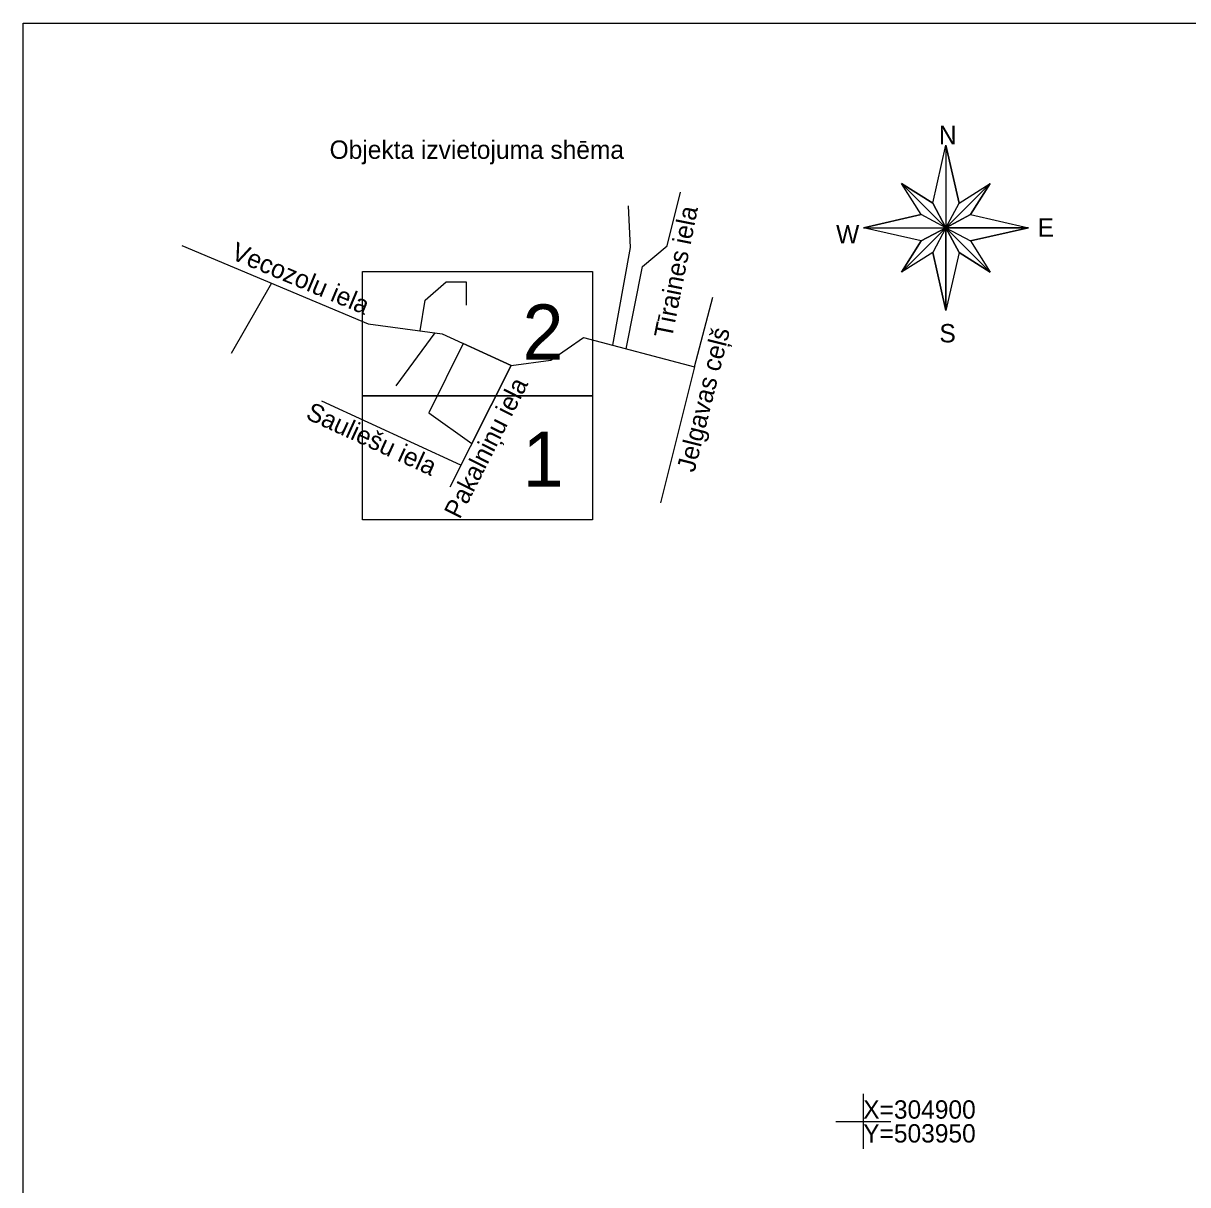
# Model space of a CAD drawing. Extents: x 503904 to 504094, y 304688 to 304960.
# Drawn here: x 503904.2 to 503967.7, y 304896.6 to 304959.8 of the extents above; entities that cross this region are included whole.
import ezdxf

# ---------------------------------------------------------------- set-up
doc = ezdxf.new("R2010")
doc.units = 0
for name, color, linetype in [('GEOD_ELEM_####_####_#', 7, 'Continuous'), ('GEOD_KORD_####_TKST_#', 7, 'Continuous'), ('RAMI_PLAN_####_TKST_#', 7, 'Continuous')]:
    doc.layers.add(name, color=color, linetype=linetype)

msp = doc.modelspace()

# ---------------------------------------------------------------- linework, layer by layer
at = {"layer": 'GEOD_ELEM_####_####_#'}
for p, q in [((503950, 304901.5), (503950, 304900)), ((503948.5, 304900), (503950, 304900)), ((503950, 304900), (503950, 304898.5)), ((503950, 304900), (503951.5, 304900))]:
    msp.add_line(p, q, dxfattribs=at)
at = {"layer": 'RAMI_PLAN_####_TKST_#'}
for p, q in [((503954.508, 304953.205), (503954.508, 304944.205)), ((503952.095, 304951.118), (503956.921, 304946.293)), ((503953.789, 304950.053), (503954.508, 304948.705)), ((503954.508, 304948.705), (503955.227, 304950.053)), ((503954.508, 304948.705), (503953.16, 304949.424)), ((503955.856, 304949.424), (503954.508, 304948.705)), ((503950.008, 304948.705), (503959.008, 304948.705)), ((503953.16, 304947.987), (503954.508, 304948.705)), ((503954.508, 304948.705), (503953.789, 304947.357)), ((503954.508, 304948.705), (503955.856, 304947.987)), ((503955.227, 304947.357), (503954.508, 304948.705)), ((503917.735, 304945.692), (503915.539, 304941.845)), ((503926.641, 304942.987), (503924.513, 304940.087)), ((503930.814, 304941.2), (503927.462, 304934.576)), ((503940.803, 304941.129), (503938.952, 304933.723)), ((503928.067, 304935.772), (503920.48, 304939.249))]:
    msp.add_line(p, q, dxfattribs=at)
for points in [[(503904.204, 304959.85), (504093.703, 304959.85), (504093.703, 304823.741), (503904.204, 304823.741)], [(503956.921, 304946.293), (503955.227, 304947.357), (503954.508, 304944.205), (503953.789, 304947.357), (503952.095, 304946.293), (503953.16, 304947.987), (503950.008, 304948.705), (503953.16, 304949.424), (503952.095, 304951.118), (503953.789, 304950.053), (503954.508, 304953.205), (503955.227, 304950.053), (503956.921, 304951.118), (503955.856, 304949.424), (503959.008, 304948.705), (503955.856, 304947.987)], [(503922.704, 304946.315), (503935.239, 304946.315), (503935.239, 304939.549), (503922.704, 304939.549)], [(503928.19, 304942.406), (503926.319, 304938.613), (503928.662, 304936.947), (503930.814, 304941.2)], [(503922.704, 304939.549), (503935.239, 304939.549), (503935.239, 304932.782), (503922.704, 304932.782)]]:
    msp.add_lwpolyline(points, close=True, dxfattribs=at)
for points in [[(503954.508, 304948.705), (503955.227, 304950.053), (503954.508, 304953.205), (503954.508, 304948.705)], [(503956.921, 304951.118), (503952.095, 304946.293)], [(503954.508, 304948.705), (503953.789, 304950.053), (503952.095, 304951.118), (503954.508, 304948.705)], [(503954.508, 304948.705), (503955.856, 304949.424), (503956.921, 304951.118), (503954.508, 304948.705)], [(503937.071, 304942.11), (503937.963, 304946.587), (503939.319, 304947.727), (503940.037, 304950.643)], [(503936.35, 304942.299), (503937.312, 304947.632), (503937.204, 304949.91)], [(503954.508, 304948.705), (503953.16, 304949.424), (503950.008, 304948.705), (503954.508, 304948.705)], [(503954.508, 304948.705), (503953.16, 304947.987), (503952.095, 304946.293), (503954.508, 304948.705)], [(503954.508, 304948.705), (503953.789, 304947.357), (503954.508, 304944.205), (503954.508, 304948.705)], [(503954.508, 304948.705), (503955.856, 304947.987), (503959.008, 304948.705), (503954.508, 304948.705)], [(503954.508, 304948.705), (503955.227, 304947.357), (503956.921, 304946.293), (503954.508, 304948.705)], [(503912.847, 304947.743), (503923.008, 304943.479), (503927.042, 304942.933), (503930.814, 304941.2), (503932.973, 304941.485), (503934.753, 304942.719), (503940.803, 304941.129), (503941.802, 304944.931)], [(503925.843, 304943.095), (503926.113, 304944.767), (503927.265, 304945.757), (503928.35, 304945.757), (503928.35, 304944.496)]]:
    msp.add_lwpolyline(points, dxfattribs=at)

# ---------------------------------------------------------------- texts
at = {"layer": 'GEOD_KORD_####_TKST_#'}
for s, p in [('X=304900', (503950, 304900.15)), ('Y=503950', (503950, 304898.85))]:
    msp.add_text(s, height=1, dxfattribs=at).set_placement(p)
at = {"layer": 'RAMI_PLAN_####_TKST_#'}
for s, height, p in [('N', 1, (503954.123, 304953.262)), ('Objekta izvietojuma shēma', 1, (503920.905, 304952.463)), ('E', 1, (503959.513, 304948.213)), ('W', 1, (503948.523, 304947.849)), ('2', 3, (503931.427, 304941.526)), ('S', 1, (503954.154, 304942.459)), ('1', 3, (503931.427, 304934.6))]:
    msp.add_text(s, height=height, dxfattribs=at).set_placement(p)
for s, rotation, p in [('Tīraines iela', 78.73924, (503939.569, 304942.636)), ('Vecozolu iela', 337.23705, (503915.472, 304947.028)), ('Jelgavas ceļš', 75.97103, (503940.796, 304935.335)), ('Pakalniņu iela', 63.15923, (503927.994, 304932.781)), ('Sauliešu iela', 335.37877, (503919.547, 304938.326))]:
    msp.add_text(s, height=1, rotation=rotation, dxfattribs=at).set_placement(p)

doc.saveas('drawing.dxf')
